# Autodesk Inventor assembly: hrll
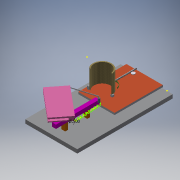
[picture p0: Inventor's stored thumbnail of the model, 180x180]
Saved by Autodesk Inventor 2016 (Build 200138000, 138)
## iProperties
Created: 2020-04
Part Number: hrll
Document SubType Name: Assembly
Designer: merlin
Author: merlin
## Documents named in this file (17)
- C:\Users\merlin\Documents\autodesk files ha\thrwoing\hrll.iam
- C:\Users\merlin\Documents\autodesk files ha\thrwoing\base.ipt
- C:\Users\merlin\Documents\autodesk files ha\thrwoing\Part2.ipt
- C:\Users\merlin\Documents\autodesk files ha\thrwoing\Part3.ipt
- C:\Users\merlin\Documents\autodesk files ha\thrwoing\Part4.ipt
- C:\Users\merlin\Documents\autodesk files ha\thrwoing\Part5.ipt
- C:\Users\merlin\Documents\autodesk files ha\thrwoing\Part7.ipt
- C:\Users\merlin\Documents\autodesk files ha\thrwoing\Part9.ipt
- C:\Users\merlin\Documents\autodesk files ha\thrwoing\Part10.ipt
- C:\Users\merlin\Documents\autodesk files ha\thrwoing\Part11.ipt
- C:\Users\merlin\Documents\autodesk files ha\thrwoing\Part12.ipt
- C:\Users\merlin\Documents\autodesk files ha\thrwoing\Part13.ipt
- C:\Users\merlin\Documents\autodesk files ha\thrwoing\Part14.ipt
- C:\Users\merlin\Documents\autodesk files ha\thrwoing\Part15.ipt
- C:\Users\merlin\Documents\autodesk files ha\thrwoing\Part16.ipt
- C:\Users\merlin\Documents\autodesk files ha\thrwoing\Part17.ipt
- C:\Users\merlin\Documents\autodesk files ha\thrwoing\Part18.ipt
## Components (23 placed, 16 different names)
1. base:1
2. Part2:1
3. Part2:2
4. Part3:1
5. Part4:1
6. Part5:1 — Mate:1
7. Part7:1
8. Part9:1 — Mate:1
9. Part2:3
10. Part2:4
11. Part10:1
12. Part11:1
13. Part12:1
14. Part12:2
15. Part13:1
16. Part14:1
17. Part14:2
18. Part15:1
19. Part16:1
20. Part16:2
21. Part17:1
22. Part17:2
23. Part18:1
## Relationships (1: Mate 1)
- Mate:1: Part5:1 ↔ Part9:1
